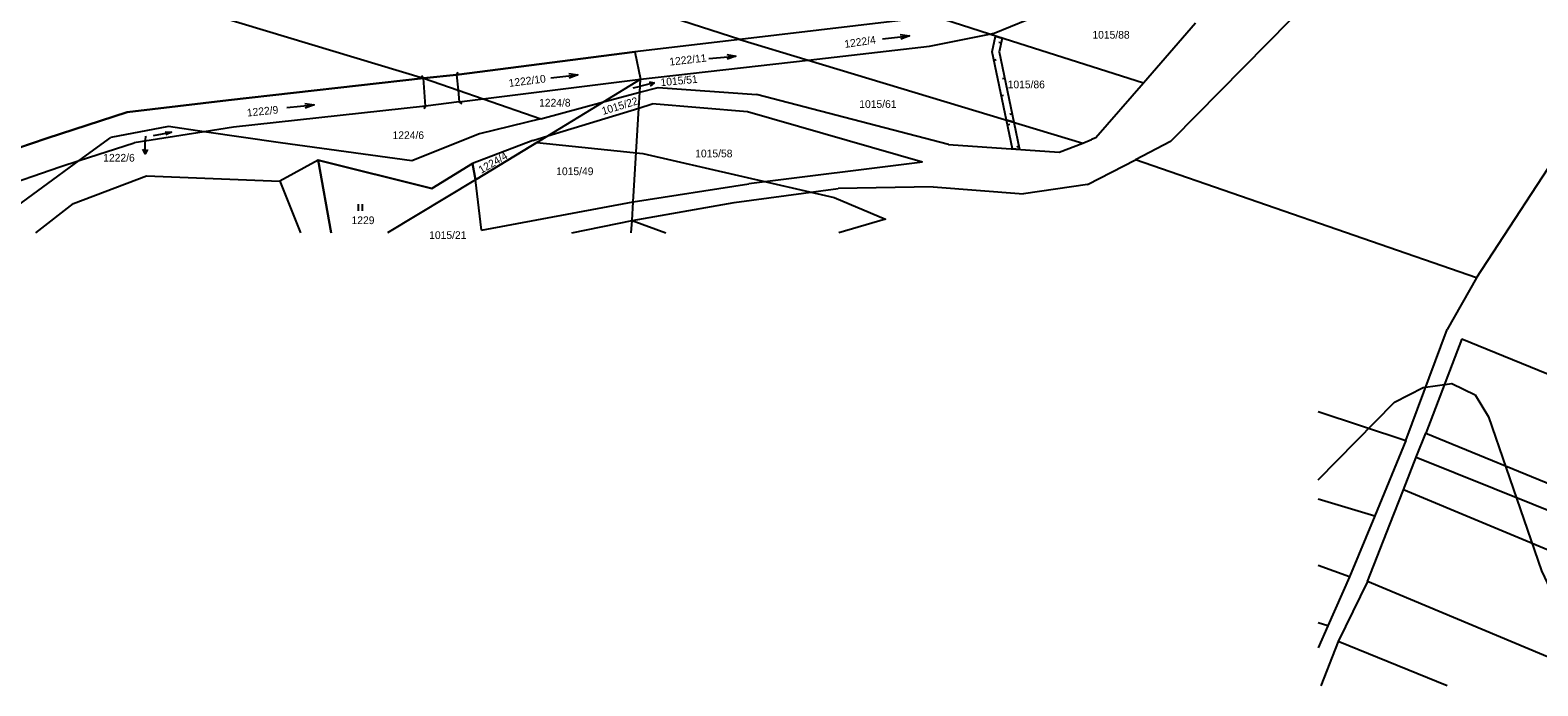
# Model space of a CAD drawing. Extents: x -777309 to -774195, y -1144706 to -1143600.
# Drawn here: x -776384.4 to -776051.5, y -1144600 to -1144455.3 of the extents above; entities that cross this region are included whole.
import ezdxf

# ---------------------------------------------------------------- set-up
doc = ezdxf.new("R2010")
doc.units = 0
for name, color, linetype in [('1', 7, 'Continuous'), ('11', 7, 'Continuous'), ('13', 7, 'Continuous'), ('2', 7, 'Continuous'), ('3', 7, 'Continuous'), ('4', 7, 'Continuous'), ('7', 7, 'Continuous')]:
    doc.layers.add(name, color=color, linetype=linetype)

msp = doc.modelspace()

# ---------------------------------------------------------------- linework, layer by layer
at = {"layer": '1'}
for p, q in [((-776471.4, -1144413.28), (-776297.5, -1144465.91)), ((-776227.64, -1144457.32), (-776310.77, -1144430.59)), ((-776087.91, -1144434.59), (-776132.08, -1144479.31)), ((-776184.7, -1144452.28), (-776227.64, -1144457.32)), ((-776172.56, -1144456.15), (-776184.7, -1144452.28)), ((-776171.5, -1144455.94), (-776160.7, -1144451.53)), ((-776127.07, -1144453.77), (-776138.57, -1144466.99)), ((-776227.64, -1144457.32), (-776250.87, -1144460.05)), ((-776227.64, -1144457.32), (-776212.6, -1144461.87)), ((-776185.82, -1144458.78), (-776172.56, -1144456.15)), ((-776172.56, -1144456.15), (-776171.5, -1144455.94)), ((-776138.57, -1144466.99), (-776172.56, -1144456.15)), ((-776290.25, -1144465.12), (-776250.87, -1144460.05)), ((-776250.87, -1144460.05), (-776249.58, -1144466.13)), ((-776212.6, -1144461.87), (-776185.82, -1144458.78)), ((-776249.58, -1144466.13), (-776212.6, -1144461.87)), ((-776212.6, -1144461.87), (-776151.92, -1144480.21)), ((-776340.57, -1144470.73), (-776297.5, -1144465.91)), ((-776297.5, -1144465.91), (-776290.25, -1144465.12)), ((-776297.5, -1144465.91), (-776289.88, -1144468.53)), ((-776284.36, -1144470.43), (-776249.58, -1144466.13)), ((-776257.75, -1144471.11), (-776249.58, -1144466.13)), ((-776249.75, -1144468.96), (-776249.58, -1144466.13)), ((-776138.57, -1144466.99), (-776149.04, -1144479.01)), ((-776362.93, -1144473.36), (-776340.57, -1144470.73)), ((-776289.88, -1144468.53), (-776284.36, -1144470.43)), ((-776289.61, -1144471.08), (-776284.36, -1144470.43)), ((-776284.36, -1144470.43), (-776271.6, -1144474.82)), ((-776257.75, -1144471.11), (-776249.75, -1144468.96)), ((-776249.96, -1144472.47), (-776249.75, -1144468.96)), ((-776249.75, -1144468.96), (-776245.68, -1144467.9)), ((-776245.68, -1144467.9), (-776224.01, -1144469.5)), ((-776181.58, -1144480.49), (-776224.01, -1144469.5)), ((-776380.6, -1144479.09), (-776362.93, -1144473.36)), ((-776297.06, -1144472.08), (-776339.5, -1144476.68)), ((-776289.61, -1144471.08), (-776297.06, -1144472.08)), ((-776271.6, -1144474.82), (-776257.75, -1144471.11)), ((-776270.03, -1144478.58), (-776257.75, -1144471.11)), ((-776270.03, -1144478.58), (-776249.96, -1144472.47)), ((-776251.22, -1144493.18), (-776249.96, -1144472.47)), ((-776249.96, -1144472.47), (-776247.06, -1144471.57)), ((-776225.96, -1144473.29), (-776247.06, -1144471.57)), ((-776187.36, -1144484.45), (-776225.96, -1144473.29)), ((-776353.84, -1144476.55), (-776366.55, -1144478.98)), ((-776345.98, -1144477.7), (-776353.84, -1144476.55)), ((-776339.5, -1144476.68), (-776345.98, -1144477.7)), ((-776271.6, -1144474.82), (-776285.18, -1144478.19)), ((-776408.5, -1144488.64), (-776380.6, -1144479.09)), ((-776373.51, -1144484.07), (-776366.55, -1144478.98)), ((-776373.51, -1144484.07), (-776361.43, -1144480.12)), ((-776345.98, -1144477.7), (-776361.43, -1144480.12)), ((-776329.12, -1144480.16), (-776345.98, -1144477.7)), ((-776300.07, -1144484.1), (-776329.12, -1144480.16)), ((-776285.18, -1144478.19), (-776300.07, -1144484.1)), ((-776273.4, -1144479.61), (-776286.69, -1144484.73)), ((-776286, -1144488.31), (-776270.03, -1144478.58)), ((-776273.4, -1144479.61), (-776270.03, -1144478.58)), ((-776181.58, -1144480.49), (-776157.18, -1144482.24)), ((-776157.18, -1144482.24), (-776151.92, -1144480.21)), ((-776151.92, -1144480.21), (-776150.02, -1144479.42)), ((-776149.04, -1144479.01), (-776150.02, -1144479.42)), ((-776132.59, -1144479.84), (-776140.32, -1144483.93)), ((-776132.08, -1144479.31), (-776132.59, -1144479.84)), ((-776064.98, -1144509.94), (-776044.3, -1144478.3)), ((-776389.57, -1144495.82), (-776373.51, -1144484.07)), ((-776377.82, -1144485.48), (-776373.51, -1144484.07)), ((-776320.81, -1144484), (-776329.23, -1144488.59)), ((-776317.9, -1144500), (-776320.81, -1144484)), ((-776320.81, -1144484), (-776295.67, -1144490.21)), ((-776150.94, -1144489.34), (-776140.32, -1144483.93)), ((-776064.98, -1144509.94), (-776140.32, -1144483.93)), ((-776398.3, -1144492.51), (-776377.82, -1144485.48)), ((-776374.79, -1144493.53), (-776358.71, -1144487.45)), ((-776358.71, -1144487.45), (-776329.23, -1144488.59)), ((-776295.67, -1144490.21), (-776286.69, -1144484.73)), ((-776286.69, -1144484.73), (-776286, -1144488.31)), ((-776187.36, -1144484.45), (-776225.71, -1144489.17)), ((-776329.23, -1144488.59), (-776324.7, -1144500)), ((-776286, -1144488.31), (-776305.5, -1144500)), ((-776284.68, -1144499.39), (-776286, -1144488.31)), ((-776251.22, -1144493.18), (-776225.71, -1144489.17)), ((-776228.95, -1144493.29), (-776205.96, -1144490.26)), ((-776184.95, -1144489.84), (-776205.96, -1144490.26)), ((-776184.95, -1144489.84), (-776165.07, -1144491.39)), ((-776150.94, -1144489.34), (-776165.07, -1144491.39)), ((-776383.09, -1144500), (-776374.79, -1144493.53)), ((-776284.68, -1144499.39), (-776251.22, -1144493.18)), ((-776251.47, -1144497.29), (-776251.22, -1144493.18)), ((-776251.47, -1144497.29), (-776228.95, -1144493.29)), ((-776264.79, -1144500), (-776251.47, -1144497.29)), ((-776251.63, -1144500), (-776251.47, -1144497.29)), ((-776251.47, -1144497.29), (-776244.04, -1144500)), ((-776064.98, -1144509.94), (-776071.46, -1144521.37)), ((-776080.59, -1144545.87), (-776071.46, -1144521.37)), ((-776068.29, -1144523.42), (-776076.23, -1144544.26)), ((-776068.29, -1144523.42), (-775962.69, -1144566.34)), ((-776100, -1144539.42), (-776080.59, -1144545.87)), ((-776080.59, -1144545.87), (-776087.49, -1144562.48)), ((-776078.31, -1144549.55), (-776076.23, -1144544.26)), ((-776076.23, -1144544.26), (-775970.99, -1144587.24)), ((-776081.14, -1144556.75), (-776078.31, -1144549.55)), ((-776078.31, -1144549.55), (-775984.37, -1144587.24)), ((-776084.14, -1144564.38), (-776081.14, -1144556.75)), ((-775977.61, -1144600), (-776081.14, -1144556.75)), ((-776100, -1144558.74), (-776087.49, -1144562.48)), ((-776087.49, -1144562.48), (-776093.07, -1144575.92)), ((-776089.09, -1144576.97), (-776084.14, -1144564.38)), ((-776093.07, -1144575.92), (-776100, -1144573.46)), ((-776093.07, -1144575.92), (-776097.85, -1144586.77)), ((-776089.09, -1144576.97), (-776095.59, -1144590.18)), ((-776034.05, -1144600), (-776089.09, -1144576.97)), ((-776097.85, -1144586.77), (-776100, -1144586.12)), ((-776097.85, -1144586.77), (-776100, -1144591.64)), ((-776095.59, -1144590.18), (-776099.39, -1144600)), ((-776071.5, -1144600), (-776095.59, -1144590.18))]:
    msp.add_line(p, q, dxfattribs=at)
at = {"layer": '11'}
for points in [[(-776184.7, -1144452.28), (-776227.64, -1144457.32), (-776250.87, -1144460.05), (-776290.25, -1144465.12), (-776297.5, -1144465.91), (-776340.57, -1144470.73), (-776362.93, -1144473.36), (-776380.6, -1144479.09), (-776408.5, -1144488.64)], [(-776272.46, -1144480.06), (-776270.03, -1144478.58), (-776257.75, -1144471.11), (-776249.58, -1144466.13), (-776212.6, -1144461.87), (-776185.82, -1144458.78), (-776172.56, -1144456.15), (-776171.5, -1144455.94), (-776160.7, -1144451.53)], [(-776272.46, -1144480.06), (-776286, -1144488.31), (-776286.69, -1144484.73), (-776295.67, -1144490.21), (-776320.81, -1144484), (-776317.9, -1144500)], [(-776272.46, -1144480.06), (-776249.09, -1144482.48), (-776206.83, -1144492.2), (-776195.48, -1144496.97), (-776205.79, -1144500)], [(-776100, -1144554.54), (-776083.12, -1144537.4), (-776076.79, -1144534.18), (-776070.45, -1144533.29), (-776065.34, -1144535.79), (-776062.33, -1144540.64), (-776050.68, -1144574.58), (-776038.68, -1144600)]]:
    msp.add_lwpolyline(points, dxfattribs=at)
at = {"layer": '13'}
for p, q in [((-776170, -1144458.09), (-776170.49, -1144457.99)), ((-776171.55, -1144461.9), (-776171.06, -1144461.79)), ((-776169.18, -1144465.92), (-776169.67, -1144466.03)), ((-776169.91, -1144469.73), (-776169.42, -1144469.62)), ((-776167.55, -1144473.75), (-776168.04, -1144473.86)), ((-776167.44, -1144481.5), (-776168.78, -1144475.11)), ((-776168.78, -1144475.11), (-776167.16, -1144475.6)), ((-776168.57, -1144476.12), (-776168.08, -1144476.01)), ((-776167.16, -1144475.6), (-776165.91, -1144481.61)), ((-776165.91, -1144481.61), (-776167.44, -1144481.5)), ((-776166.04, -1144480.98), (-776166.53, -1144481.09))]:
    msp.add_line(p, q, dxfattribs=at)
msp.add_lwpolyline([(-776168.78, -1144475.11), (-776171.93, -1144460.07), (-776171.2, -1144456.58), (-776169.78, -1144457.04), (-776170.41, -1144460.05), (-776167.16, -1144475.6)], close=True, dxfattribs=at)
at = {"layer": '3'}
for p, q in [((-776196.16, -1144457.22), (-776190.2, -1144456.54)), ((-776234.51, -1144461.53), (-776228.53, -1144460.99)), ((-776269.37, -1144465.81), (-776263.41, -1144465.11)), ((-776327.67, -1144472.38), (-776321.69, -1144471.78)), ((-776357.11, -1144478.53), (-776353.17, -1144477.79)), ((-776311.96, -1144493.66), (-776311.96, -1144495.16)), ((-776310.96, -1144495.16), (-776310.96, -1144493.66))]:
    msp.add_line(p, q, dxfattribs=at)
for points in [[(-776192.24, -1144456.27), (-776190.2, -1144456.54), (-776192.13, -1144457.26)], [(-776230.57, -1144460.67), (-776228.53, -1144460.99), (-776230.48, -1144461.67)], [(-776265.46, -1144464.85), (-776263.41, -1144465.11), (-776265.34, -1144465.84)], [(-776323.73, -1144471.48), (-776321.69, -1144471.78), (-776323.64, -1144472.48)], [(-776354.54, -1144477.71), (-776353.17, -1144477.79), (-776354.42, -1144478.36)]]:
    msp.add_lwpolyline(points, dxfattribs=at)
at = {"layer": '4'}
for p, q in [((-776297.5, -1144465.91), (-776297.97, -1144465.38)), ((-776297.06, -1144472.08), (-776297.5, -1144465.91)), ((-776290.25, -1144465.12), (-776289.85, -1144464.54)), ((-776290.25, -1144465.12), (-776289.88, -1144468.53)), ((-776289.88, -1144468.53), (-776289.61, -1144471.08)), ((-776297.06, -1144472.08), (-776297.46, -1144472.66)), ((-776289.61, -1144471.08), (-776289.04, -1144471.5))]:
    msp.add_line(p, q, dxfattribs=at)
at = {"layer": '7'}
for p, q in [((-776251.23, -1144468.03), (-776249.52, -1144467.62)), ((-776246.6, -1144466.92), (-776249.52, -1144467.62)), ((-776359, -1144482.59), (-776358.94, -1144479.59)), ((-776358.92, -1144478.67), (-776358.94, -1144479.59))]:
    msp.add_line(p, q, dxfattribs=at)
for points in [[(-776247.69, -1144466.67), (-776246.6, -1144466.92), (-776247.46, -1144467.64)], [(-776358.48, -1144481.6), (-776359, -1144482.59), (-776359.48, -1144481.58)]]:
    msp.add_lwpolyline(points, dxfattribs=at)

# ---------------------------------------------------------------- texts
at = {"layer": '2'}
for s, rotation, p in [('1222/4', 8.2506, (-776204.45, -1144459.2)), ('1222/11', 6.4171, (-776243.13, -1144463.11)), ('1222/10', 7.162, (-776278.59, -1144467.81)), ('1015/22', 16.9023, (-776257.87, -1144474)), ('1222/9', 5.7869, (-776336.42, -1144474.35)), ('1224/4', 30.2522, (-776284.75, -1144487.01))]:
    msp.add_text(s, height=1.7, rotation=rotation, dxfattribs=at).set_placement(p)
for s, height, p in [('1015/88', 1.7, (-776149.82, -1144457.15)), ('1015/86', 1.7, (-776168.53, -1144468.11)), ('1224/8', 1.7, (-776272, -1144472.14)), ('1015/51', 0.1, (-776251.21, -1144468.03)), ('1015/61', 1.7, (-776201.3, -1144472.44)), ('1224/6', 1.7, (-776304.35, -1144479.31)), ('1222/6', 0.1, (-776358.9, -1144478.67)), ('1015/58', 1.7, (-776237.52, -1144483.35)), ('1015/49', 1.7, (-776268.21, -1144487.28)), ('1229', 1.7, (-776313.4, -1144498.09)), ('1015/21', 1.7, (-776296.26, -1144501.37))]:
    msp.add_text(s, height=height, dxfattribs=at).set_placement(p)
at = {"layer": '7'}
msp.add_text('1015/51', height=1.7, rotation=5.3285, dxfattribs=at).set_placement((-776245.1, -1144467.65))
msp.add_text('1222/6', height=1.7, dxfattribs=at).set_placement((-776368.23, -1144484.29))

doc.saveas('drawing.dxf')
